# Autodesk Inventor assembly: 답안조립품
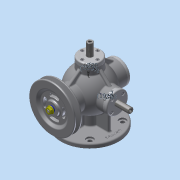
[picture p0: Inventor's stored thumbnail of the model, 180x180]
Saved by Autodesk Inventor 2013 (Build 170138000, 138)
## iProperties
Created: 2016-07
Part Number: 답안조립품
Document SubType Name: Assembly
Designer: dgall
Author: dgall
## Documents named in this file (17)
- C:\Users\dgall\Desktop\360707V1024\답안조립품.iam
- C:\Users\dgall\Desktop\360707V1024\본체.ipt
- C:\Users\dgall\Desktop\360707V1024\본체커버.ipt
- C:\Users\dgall\Desktop\360707V1024\베어링- 6202.ipt
- C:\Users\dgall\Desktop\360707V1024\앞커버.ipt
- C:\Users\dgall\Desktop\360707V1024\뒤커버.ipt
- C:\Users\dgall\Desktop\360707V1024\슬라이드 커버.ipt
- C:\Users\dgall\Desktop\360707V1024\축.ipt
- C:\Users\dgall\Desktop\360707V1024\오일실.ipt
- C:\Users\dgall\Desktop\360707V1024\키-4x4.ipt
- C:\Users\dgall\Desktop\360707V1024\V-벨트풀리.ipt
- C:\Users\dgall\Desktop\360707V1024\와셔 8x17.ipt
- C:\Users\dgall\Desktop\360707V1024\너트-M8x1.ipt
- C:\Users\dgall\Desktop\360707V1024\볼트 M4x0.7.ipt
- C:\Users\dgall\Desktop\360707V1024\슬라이드.ipt
- C:\Users\dgall\Desktop\360707V1024\스프링1.ipt
- C:\Users\dgall\Desktop\360707V1024\스프링2.ipt
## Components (18 placed, 2 different names)
1. V-벨트풀리:1 — 플러쉬:2
2. M4x0.7x12:1
3. M4x0.7x12:3
4. M4x0.7x12:6
5. M4x0.7x12:7
6. M4x0.7x12:8
7. M4x0.7x12:4
8. M4x0.7x12:9
9. M4x0.7x12:10
10. M4x0.7x12:11
11. M4x0.7x12:5
12. M4x0.7x12:12
13. M4x0.7x12:13
14. M4x0.7x12:14
15. M4x0.7x12:2
16. M4x0.7x12:15
17. M4x0.7x12:16
18. M4x0.7x12:17
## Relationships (1: Flush 1)
- 플러쉬:2 [Flush]: V-벨트풀리:1
